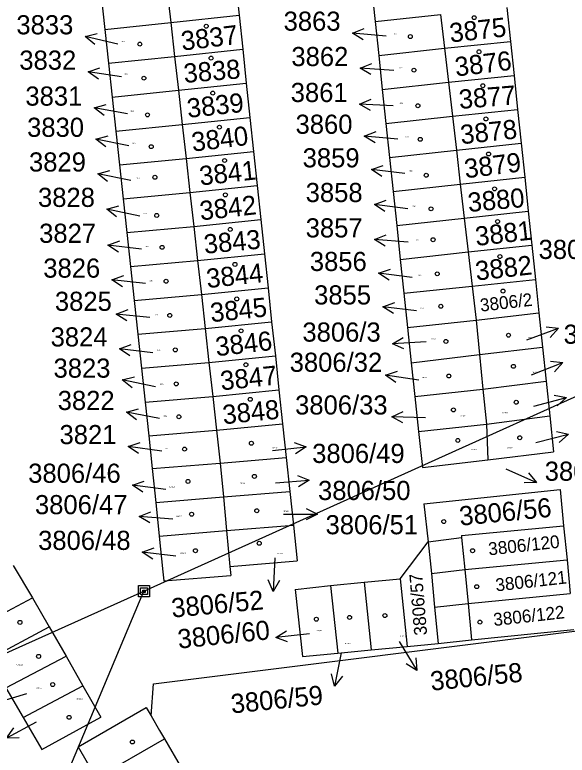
# Model space of a CAD drawing. Extents: x -735092 to -733385, y -1122435 to -1118992.
# Drawn here: x -734241.7 to -734192.6, y -1121292.4 to -1121226.6 of the extents above; entities that cross this region are included whole.
import ezdxf

# ---------------------------------------------------------------- set-up
doc = ezdxf.new("R2010")
doc.units = 0
for name, color, linetype in [('Vrstva 1', 7, 'Continuous'), ('Vrstva 12', 7, 'Continuous'), ('Vrstva 16', 7, 'Continuous'), ('Vrstva 18', 7, 'Continuous'), ('Vrstva 19', 7, 'Continuous'), ('Vrstva 25', 7, 'Continuous'), ('Vrstva 4', 7, 'Continuous')]:
    doc.layers.add(name, color=color, linetype=linetype)

msp = doc.modelspace()

# ---------------------------------------------------------------- linework, layer by layer
at = {"layer": 'Vrstva 1'}
for points in [[(-734222.07, -1121223.65), (-734221.75, -1121226.68)], [(-734228.15, -1121224.3), (-734227.81, -1121227.32)], [(-734209.98, -1121224.23), (-734209.66, -1121227.24)], [(-734233.99, -1121224.94), (-734233.67, -1121227.95)], [(-734197.95, -1121225.99), (-734197.63, -1121229.01)], [(-734227.81, -1121227.32), (-734221.75, -1121226.68)], [(-734221.75, -1121226.68), (-734221.42, -1121229.71)], [(-734209.66, -1121227.24), (-734203.85, -1121226.61)], [(-734203.85, -1121226.61), (-734203.5, -1121229.62)], [(-734233.67, -1121227.95), (-734227.81, -1121227.32)], [(-734227.81, -1121227.32), (-734227.47, -1121230.34)], [(-734209.66, -1121227.24), (-734209.34, -1121230.26)], [(-734233.67, -1121227.95), (-734233.34, -1121230.95)], [(-734203.5, -1121229.62), (-734197.63, -1121229.01)], [(-734197.63, -1121229.01), (-734197.31, -1121232.02)], [(-734227.47, -1121230.34), (-734221.42, -1121229.71)], [(-734221.42, -1121229.71), (-734221.1, -1121232.72)], [(-734209.34, -1121230.26), (-734203.5, -1121229.62)], [(-734203.5, -1121229.62), (-734203.15, -1121232.64)], [(-734233.34, -1121230.95), (-734227.47, -1121230.34)], [(-734227.47, -1121230.34), (-734227.13, -1121233.35)], [(-734209.34, -1121230.26), (-734209.02, -1121233.27)], [(-734233.34, -1121230.95), (-734233.02, -1121233.96)], [(-734203.15, -1121232.64), (-734197.31, -1121232.02)], [(-734197.31, -1121232.02), (-734197, -1121235.04)], [(-734227.13, -1121233.35), (-734221.1, -1121232.72)], [(-734221.1, -1121232.72), (-734220.78, -1121235.76)], [(-734209.02, -1121233.27), (-734203.15, -1121232.64)], [(-734203.15, -1121232.64), (-734202.79, -1121235.65)], [(-734233.02, -1121233.96), (-734227.13, -1121233.35)], [(-734227.13, -1121233.35), (-734226.79, -1121236.38)], [(-734209.02, -1121233.27), (-734208.7, -1121236.29)], [(-734233.02, -1121233.96), (-734232.69, -1121236.97)], [(-734202.79, -1121235.65), (-734197, -1121235.04)], [(-734197, -1121235.04), (-734196.68, -1121238.05)], [(-734226.79, -1121236.38), (-734220.78, -1121235.76)], [(-734220.78, -1121235.76), (-734220.46, -1121238.78)], [(-734208.7, -1121236.29), (-734202.79, -1121235.65)], [(-734202.79, -1121235.65), (-734202.44, -1121238.66)], [(-734232.69, -1121236.97), (-734226.79, -1121236.38)], [(-734226.79, -1121236.38), (-734226.45, -1121239.4)], [(-734208.7, -1121236.29), (-734208.38, -1121239.31)], [(-734232.69, -1121236.97), (-734232.37, -1121239.97)], [(-734208.38, -1121239.31), (-734202.44, -1121238.66)], [(-734202.44, -1121238.66), (-734196.68, -1121238.05)], [(-734202.44, -1121238.66), (-734202.09, -1121241.68)], [(-734196.68, -1121238.05), (-734196.37, -1121241.07)], [(-734226.45, -1121239.4), (-734220.46, -1121238.78)], [(-734220.46, -1121238.78), (-734220.13, -1121241.8)], [(-734208.38, -1121239.31), (-734208.06, -1121242.32)], [(-734232.37, -1121239.97), (-734226.45, -1121239.4)], [(-734232.37, -1121239.97), (-734232.04, -1121242.98)], [(-734226.45, -1121239.4), (-734226.11, -1121242.42)], [(-734202.09, -1121241.68), (-734196.37, -1121241.07)], [(-734196.37, -1121241.07), (-734196.05, -1121244.09)], [(-734226.11, -1121242.42), (-734220.13, -1121241.8)], [(-734220.13, -1121241.8), (-734219.81, -1121244.83)], [(-734208.06, -1121242.32), (-734202.09, -1121241.68)], [(-734202.09, -1121241.68), (-734201.74, -1121244.69)], [(-734232.04, -1121242.98), (-734226.11, -1121242.42)], [(-734226.11, -1121242.42), (-734225.77, -1121245.43)], [(-734208.06, -1121242.32), (-734207.74, -1121245.34)], [(-734232.04, -1121242.98), (-734231.72, -1121245.98)], [(-734201.74, -1121244.69), (-734196.05, -1121244.09)], [(-734196.05, -1121244.09), (-734195.74, -1121247.1)], [(-734225.77, -1121245.43), (-734219.81, -1121244.83)], [(-734219.81, -1121244.83), (-734219.49, -1121247.85)], [(-734207.74, -1121245.34), (-734201.74, -1121244.69)], [(-734201.74, -1121244.69), (-734201.39, -1121247.7)], [(-734231.72, -1121245.98), (-734225.77, -1121245.43)], [(-734225.77, -1121245.43), (-734225.43, -1121248.45)], [(-734207.74, -1121245.34), (-734207.42, -1121248.36)], [(-734231.72, -1121245.98), (-734231.39, -1121249)], [(-734201.39, -1121247.7), (-734195.74, -1121247.1)], [(-734195.74, -1121247.1), (-734195.42, -1121250.13)], [(-734225.43, -1121248.45), (-734219.49, -1121247.85)], [(-734219.49, -1121247.85), (-734219.17, -1121250.88)], [(-734207.42, -1121248.36), (-734201.39, -1121247.7)], [(-734201.39, -1121247.7), (-734201.03, -1121250.73)], [(-734231.39, -1121249), (-734225.43, -1121248.45)], [(-734225.43, -1121248.45), (-734225.09, -1121251.47)], [(-734207.42, -1121248.36), (-734207.1, -1121251.37)], [(-734231.39, -1121249), (-734231.07, -1121252.01)], [(-734201.03, -1121250.73), (-734195.42, -1121250.13)], [(-734195.42, -1121250.13), (-734195.11, -1121253.11)], [(-734225.09, -1121251.47), (-734219.17, -1121250.88)], [(-734219.17, -1121250.88), (-734218.85, -1121253.9)], [(-734207.1, -1121251.37), (-734201.03, -1121250.73)], [(-734201.03, -1121250.73), (-734200.68, -1121253.76)], [(-734231.07, -1121252.01), (-734225.09, -1121251.47)], [(-734225.09, -1121251.47), (-734224.75, -1121254.49)], [(-734207.1, -1121251.37), (-734206.78, -1121254.41)], [(-734231.07, -1121252.01), (-734230.75, -1121255.01)], [(-734200.68, -1121253.76), (-734195.11, -1121253.11)], [(-734195.11, -1121253.11), (-734194.79, -1121256.14)], [(-734206.78, -1121254.41), (-734200.68, -1121253.76)], [(-734200.68, -1121253.76), (-734200.39, -1121256.81)], [(-734224.75, -1121254.49), (-734218.85, -1121253.9)], [(-734218.85, -1121253.9), (-734218.52, -1121256.92)], [(-734206.78, -1121254.41), (-734206.45, -1121257.54)], [(-734230.75, -1121255.01), (-734224.75, -1121254.49)], [(-734230.75, -1121255.01), (-734230.42, -1121258.02)], [(-734224.75, -1121254.49), (-734224.42, -1121257.51)], [(-734200.39, -1121256.81), (-734194.79, -1121256.14)], [(-734194.79, -1121256.14), (-734194.47, -1121259.18)], [(-734224.42, -1121257.51), (-734218.52, -1121256.92)], [(-734218.52, -1121256.92), (-734218.2, -1121259.95)], [(-734206.45, -1121257.54), (-734200.39, -1121256.81)], [(-734200.39, -1121256.81), (-734200.08, -1121259.89)], [(-734230.42, -1121258.02), (-734224.42, -1121257.51)], [(-734224.42, -1121257.51), (-734224.08, -1121260.52)], [(-734206.45, -1121257.54), (-734206.13, -1121260.54)], [(-734230.42, -1121258.02), (-734230.1, -1121261.03)], [(-734200.08, -1121259.89), (-734194.47, -1121259.18)], [(-734194.47, -1121259.18), (-734194.15, -1121262.26)], [(-734224.08, -1121260.52), (-734218.2, -1121259.95)], [(-734218.2, -1121259.95), (-734217.88, -1121262.96)], [(-734206.13, -1121260.54), (-734200.08, -1121259.89)], [(-734200.08, -1121259.89), (-734199.75, -1121262.98)], [(-734230.1, -1121261.03), (-734224.08, -1121260.52)], [(-734224.08, -1121260.52), (-734223.74, -1121263.53)], [(-734206.13, -1121260.54), (-734205.8, -1121263.63)], [(-734230.1, -1121261.03), (-734229.77, -1121264.03)], [(-734199.75, -1121262.98), (-734194.15, -1121262.26)], [(-734194.15, -1121262.26), (-734193.81, -1121265.45)], [(-734223.74, -1121263.53), (-734217.88, -1121262.96)], [(-734217.88, -1121262.96), (-734217.56, -1121265.95)], [(-734205.8, -1121263.63), (-734199.75, -1121262.98)], [(-734199.75, -1121262.98), (-734199.64, -1121266.14)], [(-734229.77, -1121264.03), (-734223.74, -1121263.53)], [(-734223.74, -1121263.53), (-734223.41, -1121266.44)], [(-734205.8, -1121263.63), (-734205.46, -1121266.82)], [(-734229.77, -1121264.03), (-734229.46, -1121266.93)], [(-734199.64, -1121266.14), (-734193.81, -1121265.45)], [(-734223.41, -1121266.44), (-734217.56, -1121265.95)], [(-734217.56, -1121265.95), (-734217.24, -1121268.95)], [(-734205.46, -1121266.82), (-734199.64, -1121266.14)], [(-734229.46, -1121266.93), (-734223.41, -1121266.44)], [(-734223.41, -1121266.44), (-734223.13, -1121269.43)], [(-734229.46, -1121266.93), (-734229.15, -1121269.94)], [(-734205.33, -1121270.05), (-734193.23, -1121268.78)], [(-734193.23, -1121268.78), (-734192.91, -1121272)], [(-734229.15, -1121269.94), (-734223.13, -1121269.43)], [(-734223.13, -1121269.43), (-734217.24, -1121268.95)], [(-734223.13, -1121269.43), (-734222.85, -1121272.43)], [(-734217.24, -1121268.95), (-734216.92, -1121271.94)], [(-734229.15, -1121269.94), (-734228.84, -1121272.92)], [(-734205.33, -1121270.05), (-734204.94, -1121273.42)], [(-734222.85, -1121272.43), (-734216.92, -1121271.94)], [(-734216.92, -1121271.94), (-734216.58, -1121275.13)], [(-734201.99, -1121272.88), (-734192.91, -1121272)], [(-734192.91, -1121272), (-734192.61, -1121275.03)], [(-734228.84, -1121272.92), (-734222.85, -1121272.43)], [(-734222.85, -1121272.43), (-734222.55, -1121275.62)], [(-734228.84, -1121272.92), (-734228.51, -1121276.1)], [(-734207.42, -1121276.72), (-734204.94, -1121273.42)], [(-734204.94, -1121273.42), (-734201.97, -1121273.06)], [(-734204.94, -1121273.42), (-734204.66, -1121276.24)], [(-734201.99, -1121272.88), (-734201.97, -1121273.06)], [(-734222.55, -1121275.62), (-734216.58, -1121275.13)], [(-734201.69, -1121275.9), (-734192.61, -1121275.03)], [(-734192.61, -1121275.03), (-734192.32, -1121278.03)], [(-734241.8, -1121275.52), (-734240.09, -1121278.4)], [(-734229.36, -1121286.05), (-734148.61, -1121275.95)], [(-734228.51, -1121276.1), (-734228.43, -1121276.9)], [(-734222.55, -1121275.62), (-734222.47, -1121276.41)], [(-734204.66, -1121276.24), (-734201.69, -1121275.9)], [(-734228.43, -1121276.9), (-734222.47, -1121276.41)], [(-734210.63, -1121277.01), (-734207.42, -1121276.72)], [(-734207.42, -1121276.72), (-734206.81, -1121282.71)], [(-734204.66, -1121276.24), (-734204.37, -1121279.22)], [(-734216.77, -1121277.65), (-734213.63, -1121277.32)], [(-734213.63, -1121277.32), (-734210.63, -1121277.01)], [(-734213.63, -1121277.32), (-734212.98, -1121283.31)], [(-734210.63, -1121277.01), (-734210, -1121283.03)], [(-734216.77, -1121277.65), (-734216.1, -1121283.61)], [(-734201.39, -1121278.9), (-734192.32, -1121278.03)], [(-734245.44, -1121281.24), (-734240.09, -1121278.4)], [(-734240.09, -1121278.4), (-734238.61, -1121280.98)], [(-734204.37, -1121279.22), (-734201.39, -1121278.9)], [(-734204.37, -1121279.22), (-734204.05, -1121282.45)], [(-734243.95, -1121283.81), (-734238.61, -1121280.98)], [(-734238.61, -1121280.98), (-734237.11, -1121283.58)], [(-734201.11, -1121282.12), (-734192, -1121281.2)], [(-734206.81, -1121282.71), (-734204.05, -1121282.45)], [(-734204.05, -1121282.45), (-734201.11, -1121282.12)], [(-734216.1, -1121283.61), (-734212.98, -1121283.31)], [(-734212.98, -1121283.31), (-734210, -1121283.03)], [(-734210, -1121283.03), (-734206.81, -1121282.71)], [(-734242.46, -1121286.38), (-734237.11, -1121283.58)], [(-734237.11, -1121283.58), (-734235.61, -1121286.21)], [(-734242.46, -1121286.38), (-734240.92, -1121289.03)], [(-734240.92, -1121289.03), (-734235.61, -1121286.21)], [(-734235.61, -1121286.21), (-734234.01, -1121288.99)], [(-734229.55, -1121288.88), (-734229.36, -1121286.05)], [(-734236.05, -1121291.64), (-734229.99, -1121288.13)], [(-734229.99, -1121288.13), (-734229.55, -1121288.88)], [(-734240.92, -1121289.03), (-734239.27, -1121291.88)], [(-734239.27, -1121291.88), (-734234.01, -1121288.99)], [(-734229.55, -1121288.88), (-734228.8, -1121290.17)], [(-734228.8, -1121290.17), (-734228.37, -1121290.91)], [(-734234.44, -1121294.41), (-734228.37, -1121290.91)], [(-734228.37, -1121290.91), (-734226.85, -1121293.53)], [(-734236.05, -1121291.64), (-734234.44, -1121294.41)]]:
    msp.add_lwpolyline(points, dxfattribs=at)
at = {"layer": 'Vrstva 12'}
for points in [[(-734230.19, -1121277.82), (-734098.32, -1121218.35)], [(-734360.81, -1121336.42), (-734230.19, -1121277.82)], [(-734291.48, -1121423.67), (-734230.19, -1121277.82)]]:
    msp.add_lwpolyline(points, dxfattribs=at)
at = {"layer": 'Vrstva 25'}
for points in [[(-734210.727, -1121228.853), (-734211.677, -1121228.263), (-734210.635, -1121227.858)], [(-734234.561, -1121229.294), (-734235.425, -1121228.586), (-734234.339, -1121228.32)], [(-734232.5, -1121229.25), (-734235.425, -1121228.586)], [(-734208.69, -1121228.54), (-734211.677, -1121228.263)], [(-734234.24, -1121232.353), (-734235.16, -1121231.718), (-734234.099, -1121231.364)], [(-734210.028, -1121231.959), (-734210.993, -1121231.397), (-734209.963, -1121230.962)], [(-734208, -1121231.59), (-734210.993, -1121231.397)], [(-734232.19, -1121232.14), (-734235.16, -1121231.718)], [(-734233.726, -1121235.578), (-734234.625, -1121234.915), (-734233.554, -1121234.594)], [(-734210.071, -1121235.135), (-734211.046, -1121234.589), (-734210.024, -1121234.137)], [(-734208.05, -1121234.73), (-734211.046, -1121234.589)], [(-734231.67, -1121235.43), (-734234.625, -1121234.915)], [(-734209.667, -1121238.003), (-734210.617, -1121237.413), (-734209.575, -1121237.008)], [(-734233.589, -1121238.374), (-734234.467, -1121237.682), (-734233.387, -1121237.395)], [(-734231.53, -1121238.29), (-734234.467, -1121237.682)], [(-734207.63, -1121237.69), (-734210.617, -1121237.413)], [(-734233.419, -1121241.448), (-734234.301, -1121240.763), (-734233.223, -1121240.468)], [(-734209.054, -1121241.003), (-734209.989, -1121240.39), (-734208.938, -1121240.011)], [(-734207.01, -1121240.74), (-734209.989, -1121240.39)], [(-734231.36, -1121241.35), (-734234.301, -1121240.763)], [(-734208.799, -1121244.103), (-734209.722, -1121243.473), (-734208.663, -1121243.114)], [(-734232.619, -1121244.594), (-734233.497, -1121243.902), (-734232.417, -1121243.615)], [(-734230.56, -1121244.51), (-734233.497, -1121243.902)], [(-734206.75, -1121243.88), (-734209.722, -1121243.473)], [(-734208.763, -1121247.181), (-734209.72, -1121246.605), (-734208.684, -1121246.185)], [(-734232.465, -1121247.706), (-734233.398, -1121247.09), (-734232.345, -1121246.714)], [(-734230.42, -1121247.45), (-734233.398, -1121247.09)], [(-734206.73, -1121246.84), (-734209.72, -1121246.605)], [(-734232.09, -1121250.781), (-734233.034, -1121250.182), (-734231.988, -1121249.788)], [(-734208.417, -1121250.211), (-734209.345, -1121249.589), (-734208.29, -1121249.22)], [(-734206.37, -1121249.97), (-734209.345, -1121249.589)], [(-734230.05, -1121250.49), (-734233.034, -1121250.182)], [(-734208.035, -1121253.176), (-734208.968, -1121252.56), (-734207.915, -1121252.184)], [(-734231.709, -1121253.812), (-734232.655, -1121253.218), (-734231.611, -1121252.818)], [(-734205.99, -1121252.92), (-734208.968, -1121252.56)], [(-734229.67, -1121253.51), (-734232.655, -1121253.218)], [(-734194.468, -1121254.348), (-734193.357, -1121254.47), (-734194.121, -1121255.286)], [(-734196.17, -1121255.51), (-734193.357, -1121254.47)], [(-734207.095, -1121256.301), (-734208.124, -1121255.863), (-734207.156, -1121255.304)], [(-734205.13, -1121255.68), (-734208.124, -1121255.863)], [(-734231.445, -1121256.906), (-734232.378, -1121256.29), (-734231.325, -1121255.914)], [(-734229.4, -1121256.65), (-734232.378, -1121256.29)], [(-734195.77, -1121258.6), (-734192.979, -1121257.501)], [(-734194.093, -1121257.402), (-734192.979, -1121257.501), (-734193.726, -1121258.333)], [(-734207.822, -1121259.278), (-734208.734, -1121258.632), (-734207.669, -1121258.29)], [(-734231.239, -1121259.751), (-734232.119, -1121259.062), (-734231.04, -1121258.772)], [(-734205.77, -1121259.09), (-734208.734, -1121258.632)], [(-734229.18, -1121259.66), (-734232.119, -1121259.062)], [(-734195.55, -1121261.4), (-734192.651, -1121260.629)], [(-734193.746, -1121260.403), (-734192.651, -1121260.629), (-734193.489, -1121261.369)], [(-734230.857, -1121262.603), (-734231.748, -1121261.929), (-734230.673, -1121261.621)], [(-734228.8, -1121262.48), (-734231.748, -1121261.929)], [(-734207.183, -1121262.86), (-734208.168, -1121262.332), (-734207.154, -1121261.861)], [(-734205.17, -1121262.42), (-734208.168, -1121262.332)], [(-734193.558, -1121263.639), (-734192.465, -1121263.874), (-734193.309, -1121264.607)], [(-734195.37, -1121264.62), (-734192.465, -1121263.874)], [(-734230.669, -1121265.59), (-734231.591, -1121264.958), (-734230.532, -1121264.6)], [(-734216.842, -1121264.618), (-734215.796, -1121265.012), (-734216.74, -1121265.611)], [(-734228.62, -1121265.37), (-734231.591, -1121264.958)], [(-734218.78, -1121265.32), (-734215.796, -1121265.012)], [(-734216.548, -1121267.538), (-734215.511, -1121267.955), (-734216.466, -1121268.534)], [(-734198.05, -1121266.94), (-734195.308, -1121268.155)], [(-734196.019, -1121267.293), (-734195.308, -1121268.155), (-734196.425, -1121268.207)], [(-734230.299, -1121269.023), (-734231.222, -1121268.393), (-734230.163, -1121268.034)], [(-734218.5, -1121268.2), (-734215.511, -1121267.955)], [(-734228.25, -1121268.8), (-734231.222, -1121268.393)], [(-734229.663, -1121271.751), (-734230.62, -1121271.175), (-734229.584, -1121270.755)], [(-734215.79, -1121270.471), (-734214.79, -1121270.97), (-734215.79, -1121271.47)], [(-734227.63, -1121271.41), (-734230.62, -1121271.175)], [(-734217.79, -1121270.97), (-734214.79, -1121270.97)], [(-734229.405, -1121274.959), (-734230.338, -1121274.345), (-734229.286, -1121273.967)], [(-734227.36, -1121274.7), (-734230.338, -1121274.345)], [(-734218.57, -1121274.84), (-734218.706, -1121277.836)], [(-734230.69, -1121277.32), (-734229.69, -1121277.32), (-734229.69, -1121278.32), (-734230.69, -1121278.32), (-734230.69, -1121277.32)], [(-734218.162, -1121276.86), (-734218.706, -1121277.836), (-734219.16, -1121276.815)], [(-734230.49, -1121277.52), (-734229.89, -1121277.52), (-734229.89, -1121278.12), (-734230.49, -1121278.12), (-734230.49, -1121277.52)], [(-734230.29, -1121277.72), (-734230.09, -1121277.72), (-734230.09, -1121277.92), (-734230.29, -1121277.92), (-734230.29, -1121277.72)], [(-734217.434, -1121282.323), (-734218.482, -1121281.933), (-734217.542, -1121281.329)], [(-734215.5, -1121281.61), (-734218.482, -1121281.933)], [(-734207.52, -1121282.29), (-734205.94, -1121284.839)], [(-734212.67, -1121283.29), (-734213.252, -1121286.232)], [(-734206.042, -1121283.726), (-734205.94, -1121284.839), (-734206.892, -1121284.253)], [(-734212.568, -1121285.349), (-734213.252, -1121286.232), (-734213.548, -1121285.154)], [(-734240.62, -1121286.93), (-734243.494, -1121287.787)], [(-734239.76, -1121289.44), (-734242.401, -1121290.862)], [(-734241.283, -1121290.828), (-734242.401, -1121290.862), (-734241.757, -1121289.947)]]:
    msp.add_lwpolyline(points, dxfattribs=at)
for centre in [(-734200.86, -1121226.9), (-734224.66, -1121227.66), (-734206.53, -1121228.58), (-734230.56, -1121229.25), (-734200.43, -1121229.93), (-734224.23, -1121230.49), (-734206.21, -1121231.56), (-734230.2, -1121232.27), (-734200.09, -1121232.94), (-734224.08, -1121233.6), (-734205.86, -1121234.72), (-734229.88, -1121235.53), (-734199.82, -1121235.89), (-734223.49, -1121236.62), (-734205.65, -1121237.7), (-734229.55, -1121238.35), (-734199.58, -1121239), (-734223.03, -1121239.58), (-734229.22, -1121241.07), (-734205.12, -1121240.89), (-734199.05, -1121242.1), (-734222.96, -1121242.63), (-734204.69, -1121243.87), (-734229.06, -1121244.46), (-734198.78, -1121245), (-734222.53, -1121245.7), (-734204.51, -1121246.61), (-734228.58, -1121247.29), (-734198.57, -1121248.11), (-734222.11, -1121248.8), (-734204.14, -1121249.64), (-734228.23, -1121250.3), (-734198.3, -1121251.17), (-734221.95, -1121251.87), (-734203.82, -1121252.52), (-734227.9, -1121253.33), (-734221.56, -1121254.7), (-734197.81, -1121255.09), (-734203.37, -1121255.64), (-734227.41, -1121256.39), (-734221.14, -1121257.71), (-734197.37, -1121257.85), (-734203.11, -1121258.71), (-734227.33, -1121259.41), (-734220.75, -1121260.78), (-734197.12, -1121261.04), (-734202.7, -1121261.72), (-734227.09, -1121262.33), (-734202.31, -1121264.43), (-734196.81, -1121264.19), (-734220.65, -1121264.68), (-734226.59, -1121265.2), (-734220.38, -1121267.62), (-734226.28, -1121268.07), (-734225.96, -1121270.98), (-734220.17, -1121270.67), (-734203.56, -1121271.63), (-734219.95, -1121273.56), (-734225.62, -1121274.22), (-734201, -1121274.22), (-734200.63, -1121277.41), (-734211.93, -1121280.14), (-734208.79, -1121279.98), (-734241.21, -1121280.58), (-734214.88, -1121280.3), (-734200.35, -1121280.56), (-734239.55, -1121283.6), (-734238.3, -1121286.1), (-734236.84, -1121289.01), (-734231.22, -1121291.2)]:
    msp.add_circle(centre, 0.175, dxfattribs=at)
at = {"layer": 'Vrstva 4'}
for points in [[(-734201.97, -1121273.06), (-734201.69, -1121275.9)], [(-734201.69, -1121275.9), (-734201.39, -1121278.9)], [(-734201.39, -1121278.9), (-734201.11, -1121282.12)]]:
    msp.add_lwpolyline(points, dxfattribs=at)

# ---------------------------------------------------------------- texts
at = {"layer": 'Vrstva 16'}
for s, p in [('3833', (-734241.526, -1121228.38)), ('3863', (-734217.786, -1121228.06)), ('3832', (-734241.266, -1121231.52)), ('3862', (-734217.096, -1121231.2)), ('3861', (-734217.156, -1121234.39)), ('3831', (-734240.726, -1121234.71)), ('3830', (-734240.576, -1121237.48)), ('3860', (-734216.726, -1121237.21)), ('3859', (-734216.096, -1121240.19)), ('3829', (-734240.406, -1121240.56)), ('3858', (-734215.826, -1121243.27)), ('3828', (-734239.606, -1121243.7)), ('3827', (-734239.506, -1121246.89)), ('3857', (-734215.826, -1121246.41)), ('3806/61', (-734195.137, -1121248.32)), ('3856', (-734215.456, -1121249.39)), ('3826', (-734239.136, -1121249.98)), ('3855', (-734215.076, -1121252.36)), ('3825', (-734238.106, -1121252.93)), ('3824', (-734238.486, -1121256.09)), ('3806/3', (-734216.117, -1121255.66)), ('3806/34', (-734192.91, -1121255.85)), ('3806/32', (-734217.247, -1121258.34)), ('3823', (-734238.226, -1121258.86)), ('3822', (-734237.856, -1121261.73)), ('3806/33', (-734216.767, -1121262.13)), ('3821', (-734237.696, -1121264.76)), ('3806/49', (-734215.25, -1121266.43)), ('3806/55', (-734194.59, -1121268.01)), ('3806/46', (-734240.477, -1121268.19)), ('3806/50', (-734214.73, -1121269.72)), ('3806/47', (-734239.877, -1121270.98)), ('3806/51', (-734214.06, -1121272.76)), ('3806/48', (-734239.597, -1121274.15))]:
    msp.add_text(s, height=1.7, dxfattribs=at).set_placement(p)
for s, rotation, p in [('3806/52', 5.20004, (-734227.688, -1121280.161)), ('3806/60', 5.90005, (-734227.113, -1121282.919)), ('3806/58', 5.70004, (-734204.673, -1121286.651)), ('3806/59', 5.70004, (-734222.397, -1121288.671))]:
    msp.add_text(s, height=1.7, rotation=rotation, dxfattribs=at).set_placement(p)
at = {"layer": 'Vrstva 18'}
msp.add_text('3806/57', height=1.14, rotation=94.70075, dxfattribs=at).set_placement((-734205.035, -1121281.698))
at = {"layer": 'Vrstva 19'}
for s, height, rotation, p in [('3875', 1.7, 6.30005, (-734202.964, -1121229.11)), ('3837', 1.7, 6.80005, (-734226.796, -1121229.828)), ('3876', 1.7, 6.90006, (-734202.476, -1121232.128)), ('3838', 1.7, 4.70004, (-734226.608, -1121232.695)), ('3877', 1.7, 4.60004, (-734202.157, -1121235.005)), ('3839', 1.7, 6.20005, (-734226.283, -1121235.8)), ('3878', 1.7, 6.00005, (-734202.003, -1121238.141)), ('3840', 1.7, 6.90006, (-734225.866, -1121238.798)), ('3879', 1.7, 7.10006, (-734201.627, -1121241.167)), ('3841', 1.7, 6.20005, (-734225.183, -1121241.8)), ('3880', 1.7, 5.10004, (-734201.359, -1121244.154)), ('3842', 1.7, 6.30005, (-734225.154, -1121244.9)), ('3881', 1.7, 6.50005, (-734200.674, -1121247.169)), ('3843', 1.7, 5.30004, (-734224.8, -1121247.863)), ('3882', 1.7, 6.30005, (-734200.664, -1121250.24)), ('3844', 1.7, 6.10005, (-734224.563, -1121250.91)), ('3845', 1.7, 6.00005, (-734224.223, -1121253.941)), ('3806/2', 1.14, 6.50005, (-734200.274, -1121252.999)), ('3846', 1.7, 6.40005, (-734223.754, -1121256.959)), ('3847', 1.7, 6.00005, (-734223.323, -1121259.991)), ('3848', 1.7, 5.80005, (-734223.132, -1121263.001)), ('3806/56', 1.7, 5.60004, (-734202.101, -1121272.002)), ('3806/120', 1.14, 6.20005, (-734199.543, -1121274.64)), ('3806/121', 1.14, 6.50005, (-734198.904, -1121277.839)), ('3806/122', 1.14, 6.30005, (-734199.094, -1121280.91))]:
    msp.add_text(s, height=height, rotation=rotation, dxfattribs=at).set_placement(p)
for s, p in [('3863', (-734208.03, -1121228.38)), ('3833', (-734232.19, -1121229.07)), ('3862', (-734207.55, -1121231.41)), ('3832', (-734231.93, -1121231.95)), ('3861', (-734207.5, -1121234.55)), ('3831', (-734231.39, -1121235.24)), ('3830', (-734231.23, -1121238.11)), ('3860', (-734206.97, -1121237.53)), ('3859', (-734206.65, -1121240.56)), ('3829', (-734230.91, -1121241.2)), ('3858', (-734206.38, -1121243.7)), ('3828', (-734230.22, -1121244.34)), ('3827', (-734230.06, -1121247.27)), ('3857', (-734206.07, -1121246.68)), ('3856', (-734205.85, -1121249.81)), ('3826', (-734229.74, -1121250.3)), ('3855', (-734205.64, -1121252.74)), ('3825', (-734229.21, -1121253.33)), ('3806/3', (-734204.67, -1121255.46)), ('3806/34', (-734196.05, -1121255.34)), ('3824', (-734229.05, -1121256.47)), ('3806/35', (-734195.68, -1121258.44)), ('3806/32', (-734205.5, -1121258.9)), ('3823', (-734228.78, -1121259.5)), ('3822', (-734228.46, -1121262.31)), ('3806/33', (-734202.13, -1121262.3)), ('3806/53', (-734198.37, -1121262.01)), ('3821', (-734228.3, -1121265.19)), ('3806/49', (-734218.82, -1121265.14)), ('3806/55', (-734201.12, -1121265.29)), ('3806/54', (-734197.92, -1121265.12)), ('3806/50', (-734221.67, -1121268.28)), ('3806/46', (-734227.95, -1121268.61)), ('3806/51', (-734217.8, -1121270.77)), ('3806/47', (-734227.34, -1121271.22)), ('3806/48', (-734226.981, -1121274.5)), ('3806/52', (-734218.36, -1121274.52)), ('3806/60', (-734214.88, -1121281.36)), ('3806/58', (-734207.47, -1121281.85)), ('3806/59', (-734212.35, -1121282.5)), ('3806/113', (-734241.54, -1121284.41)), ('3806/114', (-734239.809, -1121286.46)), ('3806/115', (-734236.19, -1121287.43))]:
    msp.add_text(s, height=0.1, dxfattribs=at).set_placement(p)

doc.saveas('drawing.dxf')
